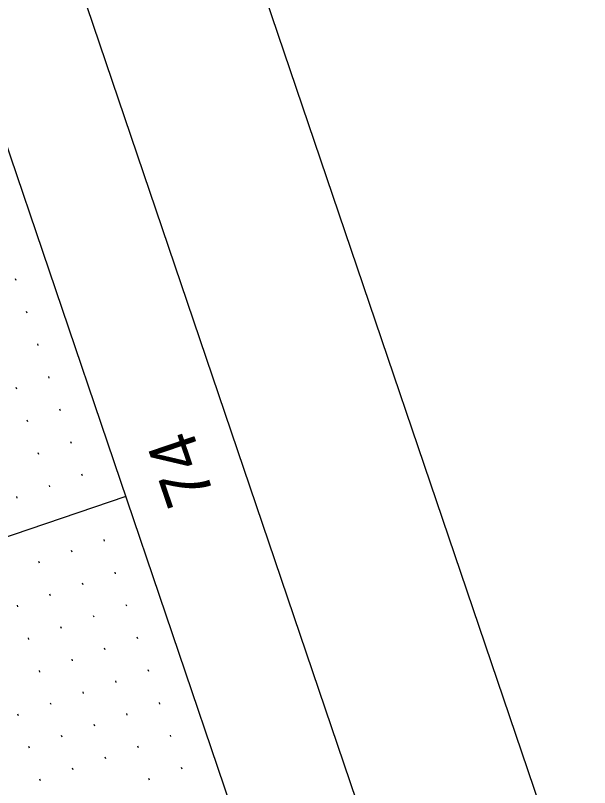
# Model space of a CAD drawing. Extents: x 2150800 to 2152547, y 141860 to 143950.
# Drawn here: x 2152301.3 to 2152384.7, y 142470.9 to 142583.1 of the extents above; entities that cross this region are included whole.
import ezdxf

# ---------------------------------------------------------------- set-up
doc = ezdxf.new("R2010")
doc.units = 0
for name, color, linetype in [('SHT_Plan_Profile_Sheet_Sta_Txt', 7, 'Continuous'), ('SHT_Plot_Shape_Half', 7, 'Continuous'), ('SHT_Profile_Grid_Major', 7, 'Continuous'), ('SHT_Profile_Grid_Minor', 7, 'Continuous'), ('SHT_Sheet_Border', 7, 'Continuous')]:
    doc.layers.add(name, color=color, linetype=linetype)

msp = doc.modelspace()

# ---------------------------------------------------------------- linework, layer by layer
at = {"layer": 'SHT_Plot_Shape_Half'}
msp.add_lwpolyline([(2151391.39, 141950.92), (2150845.24, 143560.8), (2151886.93, 143914.19), (2152433.08, 142304.31)], close=True, dxfattribs=at)
at = {"layer": 'SHT_Profile_Grid_Major'}
msp.add_line((2152317.33, 142513.2), (2151867.44, 142360.57), dxfattribs=at)
at = {"layer": 'SHT_Profile_Grid_Minor'}
for p, q in [((2152301.4, 142544.62), (2152301.32, 142544.85)), ((2152303, 142539.88), (2152302.92, 142540.12)), ((2152304.61, 142535.15), (2152304.53, 142535.38)), ((2152306.21, 142530.41), (2152306.13, 142530.65)), ((2152301.48, 142528.81), (2152301.4, 142529.04)), ((2152307.82, 142525.68), (2152307.74, 142525.91)), ((2152303.09, 142524.07), (2152303.01, 142524.31)), ((2152309.43, 142520.94), (2152309.35, 142521.18)), ((2152304.69, 142519.34), (2152304.61, 142519.57)), ((2152311.03, 142516.21), (2152310.95, 142516.44)), ((2152306.3, 142514.6), (2152306.22, 142514.84)), ((2152301.56, 142512.99), (2152301.48, 142513.23)), ((2152314.25, 142506.74), (2152314.17, 142506.97)), ((2152309.51, 142505.13), (2152309.43, 142505.37)), ((2152304.78, 142503.52), (2152304.7, 142503.76)), ((2152315.85, 142502), (2152315.77, 142502.24)), ((2152311.12, 142500.4), (2152311.04, 142500.63)), ((2152306.38, 142498.79), (2152306.3, 142499.03)), ((2152301.65, 142497.18), (2152301.57, 142497.42)), ((2152317.46, 142497.27), (2152317.38, 142497.5)), ((2152312.72, 142495.66), (2152312.64, 142495.9)), ((2152307.99, 142494.05), (2152307.91, 142494.29)), ((2152303.25, 142492.45), (2152303.17, 142492.68)), ((2152319.07, 142492.53), (2152318.98, 142492.77)), ((2152314.33, 142490.93), (2152314.25, 142491.16)), ((2152309.6, 142489.32), (2152309.52, 142489.56)), ((2152304.86, 142487.71), (2152304.78, 142487.95)), ((2152320.67, 142487.8), (2152320.59, 142488.03)), ((2152315.94, 142486.19), (2152315.86, 142486.43)), ((2152311.2, 142484.58), (2152311.12, 142484.82)), ((2152306.47, 142482.98), (2152306.39, 142483.21)), ((2152322.28, 142483.06), (2152322.2, 142483.3)), ((2152301.73, 142481.37), (2152301.65, 142481.61)), ((2152317.54, 142481.46), (2152317.46, 142481.69)), ((2152312.81, 142479.85), (2152312.73, 142480.09)), ((2152308.07, 142478.24), (2152307.99, 142478.48)), ((2152323.88, 142478.33), (2152323.8, 142478.56)), ((2152303.34, 142476.64), (2152303.26, 142476.87)), ((2152319.15, 142476.72), (2152319.07, 142476.96)), ((2152314.41, 142475.11), (2152314.33, 142475.35)), ((2152309.68, 142473.51), (2152309.6, 142473.75)), ((2152325.49, 142473.59), (2152325.41, 142473.83)), ((2152304.94, 142471.9), (2152304.86, 142472.14)), ((2152320.76, 142471.99), (2152320.68, 142472.22))]:
    msp.add_line(p, q, dxfattribs=at)
at = {"layer": 'SHT_Sheet_Border'}
msp.add_line((2152361.51, 142382.99), (2151939.85, 143625.91), dxfattribs=at)
msp.add_lwpolyline([(2151383.74, 142051.28), (2150877.75, 143542.79), (2151872.09, 143880.12), (2152378.08, 142388.61)], close=True, dxfattribs=at)

# ---------------------------------------------------------------- texts
at = {"layer": 'SHT_Plan_Profile_Sheet_Sta_Txt'}
msp.add_text('74', height=7, rotation=108.7393, dxfattribs=at).set_placement((2152330.25, 142513.25))

doc.saveas('drawing.dxf')
